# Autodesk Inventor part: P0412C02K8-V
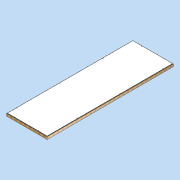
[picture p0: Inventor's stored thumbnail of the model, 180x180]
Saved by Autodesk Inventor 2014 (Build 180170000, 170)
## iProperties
Created: 2011-04
Part Number: P0412C02K8-V
Document SubType Name: Modeling
Designer: david.appleford
Density: 0.192991 g/cm^3
Description: 1w x 3w 02 Ceiling Panel - 8 Locks
Mass: 66000 g
Surface Area: 90482.9 cm^2
Volume: 341985 cm^3
Cost Center: £200.00
Material: Generic
Appearance: Wood (Pine)
Justset: False
Author: david.appleford
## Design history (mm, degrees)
sketch "Sketch1"
  geometry: L1 (0, 0)-(1220, 0); L2 (1220, 0)-(1220, 3660); L3 (1220, 3660)-(0, 3660); L4 (0, 3660)-(0, 0); L5 (34, 3626)-(1186, 3626); L6 (1186, 3626)-(1186, 34); L7 (1186, 34)-(34, 34); L8 (34, 34)-(34, 3626)
  constraints: 16 end point, 4 parallel, 2 perpendicular, 1 horizontal, 3 other
  dimensions: "d0" = 1220 distance between parallel lines of L2 L4 (= w); "d1" = 3660 distance between parallel lines of L1 L3 (= 3 x w); "d2" = 34 distance between parallel lines of L5 L3 (= 0.5 x t)
extrude "Extrusion1" new body sketch "Sketch1" distance "d3" = 68 (= t); taper "d4" = 0 deg
sketch "Sketch2"
  geometry: L1 (1186, 3626)-(1186, 34) reference; L2 (34, 3626)-(1186, 3626) reference; L3 (34, 34)-(34, 3626) reference; L4 (1186, 34)-(34, 34) reference; L5 (1176, 3616)-(1176, 44); L6 (1176, 44)-(44, 44); L7 (44, 44)-(44, 3616); L8 (44, 3616)-(1176, 3616); 1 further point
  constraints: 8 end point, 3 other
  dimensions: "d5" = 10 distance between parallel lines of L8 L2
extrude "Extrusion2" join sketch "Sketch2" distance "d6" = 9; taper "d7" = 0 deg
sketch "Sketch3"
  geometry: L1 (-44, 3616)-(-1176, 3616) reference; L2 (-1176, 3616)-(-1176, 44) reference; L3 (-44, 44)-(-44, 3616) reference; L4 (-1176, 44)-(-44, 44) reference; 1 further point
extrude "Extrusion3" join sketch "Sketch3" distance "d8" = 6 (= sw); taper "d9" = 0 deg
sketch "Sketch4"
  geometry: L1 (34, 3626)-(1186, 3626) reference; L2 (1186, 3626)-(1186, 34) reference; L3 (1186, 34)-(34, 34) reference; L4 (34, 34)-(34, 3626) reference; 9 further points
  constraints: 4 vertical alignment
  dimensions: "d10" = 28 distance from line of point (305, 3598) L1 (= k); "d11" = 28 distance from line of L2 point (1158, 3355) (= k); "d12" = 28 distance from line of L3 point (915, 62) (= k); "d13" = 28 distance from line of point (62, 305) L4 (= k); "d14" = 305 horizontal distance of point (305, 3598) point (0, 0) (= 0.25 x w); "d15" = 610 horizontal distance of point (915, 62) point (305, 3598) (= 0.5 x w); "d16" = 305 vertical distance of point (62, 305) point (0, 0) (= 0.25 x w); "d17" = 1220 distance of point (62, 305) point (62, 1525) (= w); "d18" = 1220 distance of point (62, 2745) point (62, 1525) (= w); "d19" = 610 vertical distance of point (1158, 915) point (62, 305) (= 0.5 x w); "d20" = 1220 distance of point (1158, 915) point (1158, 2135) (= w); "d21" = 1220 distance of point (1158, 3355) point (1158, 2135) (= w)
hole "Hole1" sketch "Sketch4" at (305, 3598), (62, 2745), (62, 1525), (62, 305), (1158, 3355), (1158, 2135), (1158, 915), (915, 62) diameter "d22" = 12 (= hd); stored, may be unused: countersink angle "d26" = 90 deg, drill point angle "d28" = 118 deg; dims "d23" = 6, "d24" = 4, "d25" = 2, "d27" = 8
chamfer "Chamfer1" distance "d29" = 3; stored, may be unused: second distance "d30" = 2, angle "d31" = 45 deg
body "Solid1"
node "Projected Loop1"
other parameters: "w" = 1220 [user parameter; used in 10 equation terms], "t" = 68 [user parameter; used in 2 equation terms], "e" = 16 [user parameter], "sw" = 6 [user parameter; used in 1 equation term], "sc" = 9 [user parameter], "sf" = 12 [user parameter], "k" = 28 [user parameter; used in 4 equation terms], "hd" = 12 [user parameter; used in 1 equation term]
